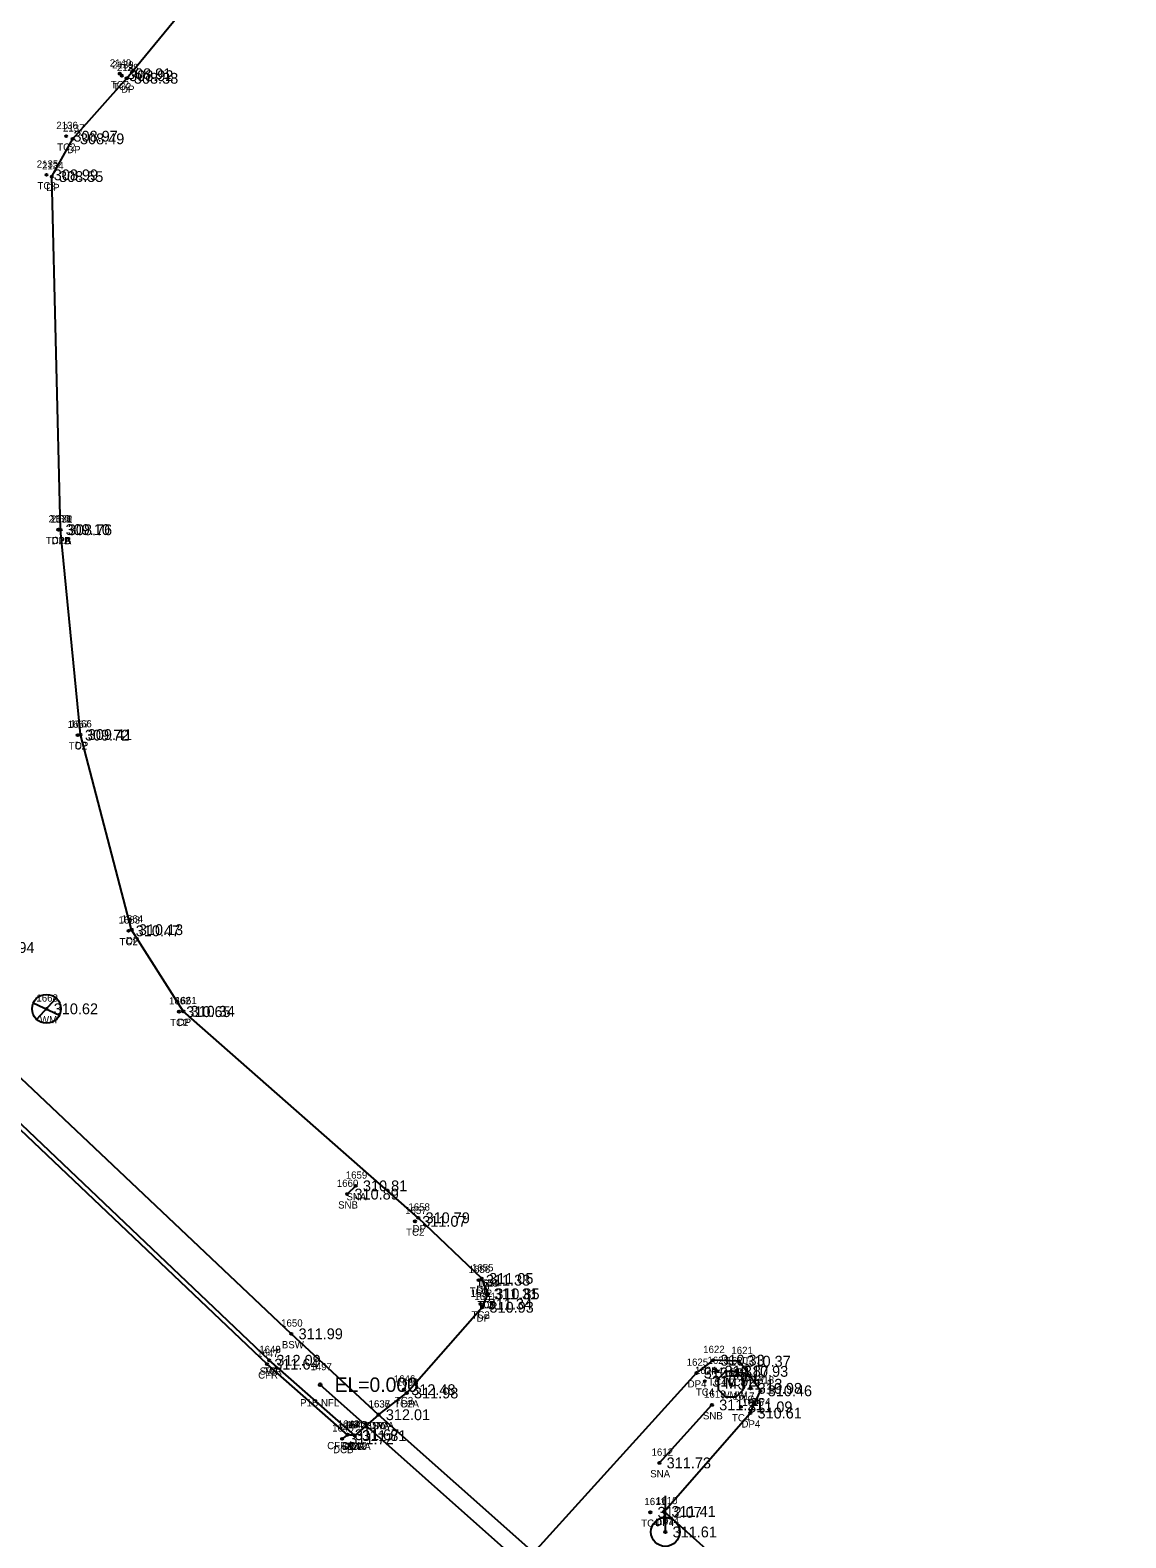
# Model space of a CAD drawing. Extents: x 1970076 to 1971136, y 803126 to 804215.
# Drawn here: x 1970777.2 to 1970928.9, y 803378.3 to 803587.1 of the extents above; entities that cross this region are included whole.
import ezdxf

# ---------------------------------------------------------------- set-up
doc = ezdxf.new("R2010")
doc.units = 0
for name, color, linetype in [('RD_EX_BldgApp', 7, 'Continuous'), ('RD_EX_BldgApp_txCode', 7, 'Continuous'), ('RD_EX_Conc', 7, 'Continuous'), ('RD_EX_Conc_txCode', 7, 'Continuous'), ('RD_EX_DR_Pipe', 7, 'Continuous'), ('RD_EX_DR_Pipe_txCode', 7, 'Continuous'), ('RD_EX_Driveway', 7, 'Continuous'), ('RD_EX_Driveway_txCode', 7, 'Continuous'), ('RD_EX_Misc_txCode', 7, 'Continuous'), ('RD_EX_SU_H2O', 7, 'Continuous'), ('RD_EX_TX_BldgApp_ELEV', 7, 'Continuous'), ('RD_EX_TX_Conc_ELEV', 7, 'Continuous'), ('RD_EX_TX_Driveway_ELEV', 7, 'Continuous'), ('RD_EX_TX_Misc_ELEV', 7, 'Continuous'), ('RD_EX_TX_UT_ELEV', 7, 'Continuous'), ('RD_EX_UT', 7, 'Continuous'), ('RD_EX_UT_txCode', 7, 'Continuous'), ('RD_SMD_Locator', 7, 'Continuous'), ('RD_TX_Pipe_ElevEX', 7, 'Continuous')]:
    doc.layers.add(name, color=color, linetype=linetype)

msp = doc.modelspace()

# ---------------------------------------------------------------- linework, layer by layer
at = {"layer": 'RD_EX_BldgApp'}
for p, q in [((1970822.26, 803427.05), (1970821.09, 803425.91)), ((1970864.31, 803388.69), (1970871.58, 803396.72))]:
    msp.add_line(p, q, dxfattribs=at)
at = {"layer": 'RD_EX_Conc'}
for points in [[(1970822.14, 803392.47), (1970810.28, 803402.9), (1970754.12, 803456.32), (1970718.38, 803492.24), (1970721.52, 803495.16)], [(1970825.43, 803395.36), (1970813.35, 803406.56), (1970757.19, 803459.64), (1970721.52, 803495.16)], [(1970821.14, 803392.59), (1970809.99, 803402.36), (1970753.68, 803455.87), (1970717.79, 803491.63)], [(1970847.44, 803368.09), (1970847.23, 803370.61), (1970846.91, 803376.25), (1970825.43, 803395.36), (1970822.14, 803392.47), (1970821.14, 803392.59), (1970820.38, 803392.03)]]:
    msp.add_lwpolyline(points, dxfattribs=at)
at = {"layer": 'RD_EX_DR_Pipe'}
msp.add_line((1971022.85, 803216.85), (1970817.34, 803399.52), dxfattribs=at)
at = {"layer": 'RD_EX_Driveway'}
for points in [[(1970781.41, 803517.89), (1970780.19, 803566.79), (1970783.09, 803572.02), (1970790.56, 803580.4), (1970803.75, 803596.41), (1970815.3, 803608.83), (1970835.93, 803622.28), (1970852.1, 803631.42), (1970860.94, 803643.71), (1970861.75, 803649.17), (1970862.81, 803650.51), (1970861.9, 803654.38), (1970859.56, 803656.74), (1970855.07, 803659.55), (1970853.81, 803659.78), (1970849.95, 803660.12)], [(1970825.43, 803395.36), (1970829.33, 803398.37), (1970839.78, 803410.24), (1970840.58, 803412.09), (1970839.73, 803414.23), (1970830.93, 803422.63), (1970798.4, 803451.22), (1970791.24, 803462.52), (1970784.17, 803489.53), (1970781.41, 803517.89)], [(1970978.49, 803349.37), (1970974.36, 803344.54), (1970973.43, 803342.01), (1970974.82, 803339.34), (1970978.6, 803335.88), (1970962.13, 803321.3), (1970960.21, 803322.85), (1970957.7, 803323.38), (1970955.12, 803322.32), (1970943.79, 803311.55), (1970935.6, 803318.56), (1970864.97, 803381.97), (1970876.89, 803395.59), (1970878.3, 803398.67), (1970875.35, 803402.77), (1970871.74, 803402.91), (1970869.45, 803401.14), (1970846.9, 803376.22)]]:
    msp.add_lwpolyline(points, dxfattribs=at)
at = {"layer": 'RD_EX_SU_H2O'}
msp.add_lwpolyline([(1970875.95, 803398.85), (1970875.95, 803400.31), (1970874.92, 803401.33), (1970873.47, 803401.33), (1970872.44, 803400.31), (1970872.44, 803398.85), (1970873.47, 803397.83), (1970874.92, 803397.83)], close=True, dxfattribs=at)
at = {"layer": 'RD_EX_UT'}
for p, q in [((1970778.11, 803450.11), (1970780.77, 803453)), ((1970777.63, 803452.4), (1970781.26, 803450.69)), ((1970865.13, 803379.13), (1970865.13, 803384.13))]:
    msp.add_line(p, q, dxfattribs=at)
for centre in [(1970779.46, 803451.56), (1970865.13, 803379.13)]:
    msp.add_circle(centre, 2, dxfattribs=at)
at = {"layer": 'RD_SMD_Locator'}
for centre, radius in [((1970789.6, 803581.03), 0.15), ((1970789.89, 803580.76), 0.15), ((1970790.56, 803580.4), 0.15), ((1970782.19, 803572.38), 0.15), ((1970783.09, 803572.02), 0.15), ((1970779.46, 803567.03), 0.15), ((1970780.19, 803566.79), 0.15), ((1970781.1, 803517.91), 0.15), ((1970781.1, 803517.91), 0.15), ((1970781.41, 803517.89), 0.15), ((1970781.41, 803517.89), 0.15), ((1970783.78, 803489.46), 0.15), ((1970784.17, 803489.53), 0.15), ((1970790.81, 803462.36), 0.15), ((1970791.24, 803462.52), 0.15), ((1970779.46, 803451.56), 0.15), ((1970797.81, 803451.17), 0.15), ((1970798.4, 803451.22), 0.15), ((1970821.09, 803425.91), 0.15), ((1970822.26, 803427.05), 0.15), ((1970830.48, 803422.14), 0.15), ((1970830.93, 803422.63), 0.15), ((1970839.29, 803413.99), 0.15), ((1970839.73, 803414.23), 0.15), ((1970839.54, 803410.68), 0.15), ((1970840.37, 803412.09), 0.15), ((1970840.58, 803412.09), 0.15), ((1970839.78, 803410.24), 0.15), ((1970813.35, 803406.56), 0.15), ((1970809.99, 803402.36), 0.15), ((1970810.28, 803402.9), 0.15), ((1970810.28, 803402.9), 0.15), ((1970871.74, 803402.91), 0.15), ((1970875.35, 803402.77), 0.15), ((1970869.45, 803401.14), 0.15), ((1970872.33, 803401.4), 0.15), ((1970875, 803401.36), 0.15), ((1970817.34, 803399.52), 0.2), ((1970828.94, 803398.83), 0.15), ((1970829.33, 803398.37), 0.15), ((1970829.33, 803398.37), 0.15), ((1970870.6, 803400), 0.15), ((1970874.19, 803399.58), 0.15), ((1970876.91, 803399.01), 0.15), ((1970878.3, 803398.67), 0.15), ((1970871.58, 803396.72), 0.15), ((1970875.59, 803396.45), 0.15), ((1970825.43, 803395.36), 0.15), ((1970825.43, 803395.36), 0.15), ((1970825.43, 803395.36), 0.15), ((1970876.89, 803395.59), 0.15), ((1970820.38, 803392.03), 0.15), ((1970821.14, 803392.59), 0.15), ((1970821.14, 803392.59), 0.15), ((1970822.14, 803392.47), 0.15), ((1970822.14, 803392.47), 0.15), ((1970822.14, 803392.47), 0.15), ((1970864.31, 803388.69), 0.15), ((1970863.04, 803381.85), 0.15), ((1970864.97, 803381.97), 0.15), ((1970865.13, 803379.13), 0.15)]:
    msp.add_circle(centre, radius, dxfattribs=at)

# ---------------------------------------------------------------- texts
at = {"layer": 'RD_EX_BldgApp_txCode'}
for s, p in [('1660', (1970819.65, 803426.91)), ('1659', (1970820.89, 803428.05)), ('SNA', (1970820.99, 803425.05)), ('SNB', (1970819.83, 803423.91)), ('1613', (1970870.49, 803397.72)), ('SNB', (1970870.33, 803394.72)), ('1612', (1970863.22, 803389.69)), ('SNA', (1970863.04, 803386.69))]:
    msp.add_text(s, height=1, dxfattribs=at).set_placement(p)
at = {"layer": 'RD_EX_Conc_txCode'}
for s, p in [('2140', (1970788.22, 803582.03)), ('2139', (1970788.54, 803581.76)), ('TC2', (1970788.36, 803579.03)), ('TC2', (1970788.65, 803578.76)), ('2136', (1970780.82, 803573.38)), ('TC2', (1970780.94, 803570.38)), ('2135', (1970778.11, 803568.03)), ('TC2', (1970778.21, 803565.03)), ('2133', (1970779.75, 803518.91)), ('1671', (1970780.01, 803518.91)), ('TC2A', (1970779.36, 803515.91)), ('TC2B', (1970779.38, 803515.91)), ('1667', (1970782.39, 803490.46)), ('TC2', (1970782.54, 803487.46)), ('1663', (1970789.42, 803463.36)), ('TC2', (1970789.57, 803460.36)), ('1662', (1970796.42, 803452.17)), ('TC2', (1970796.57, 803449.17)), ('1657', (1970829.11, 803423.14)), ('TC2', (1970829.24, 803420.14)), ('1656', (1970837.9, 803414.99)), ('TC2', (1970838.05, 803411.99)), ('1653', (1970839, 803413.09)), ('1652', (1970838.17, 803411.68)), ('TC2', (1970839.13, 803410.09)), ('TC2', (1970838.3, 803408.68)), ('1650', (1970811.94, 803407.56)), ('1648', (1970808.91, 803403.9)), ('1649', (1970808.91, 803403.9)), ('BSW', (1970812.04, 803404.56)), ('1647', (1970808.62, 803403.36)), ('1623', (1970870.96, 803402.4)), ('1620', (1970873.59, 803402.36)), ('CFR', (1970808.76, 803400.36)), ('SWR', (1970808.97, 803400.9)), ('TC', (1970809.49, 803400.9)), ('1646', (1970827.54, 803399.83)), ('1639', (1970827.96, 803399.37)), ('1624', (1970869.23, 803401)), ('TC4', (1970871.08, 803399.4)), ('TC4', (1970873.76, 803399.36)), ('1619', (1970875.82, 803400.01)), ('TC4', (1970869.35, 803398)), ('1617', (1970874.5, 803397.45)), ('1635', (1970824.06, 803396.36)), ('1637', (1970824.06, 803396.36)), ('TC2A', (1970827.6, 803396.37)), ('TC2', (1970827.69, 803396.83)), ('TC4', (1970875.66, 803397.01)), ('1645', (1970819.01, 803393.03)), ('1643', (1970819.77, 803393.59)), ('1644', (1970819.77, 803393.59)), ('1640', (1970820.73, 803393.47)), ('1642', (1970820.77, 803393.47)), ('1641', (1970821.05, 803393.47)), ('BSWA', (1970823.63, 803393.36)), ('DC', (1970824.65, 803393.36)), ('TC4', (1970874.35, 803394.45)), ('CFRA 12', (1970818.32, 803390.59)), ('DCB', (1970819.13, 803390.03)), ('SWRA', (1970820.33, 803390.47)), ('DC', (1970820.36, 803390.59)), ('TCA', (1970820.85, 803390.47)), ('DC', (1970821.36, 803390.47)), ('1611', (1970862.23, 803382.85)), ('TC4', (1970861.79, 803379.85))]:
    msp.add_text(s, height=1, dxfattribs=at).set_placement(p)
at = {"layer": 'RD_EX_DR_Pipe_txCode'}
for s, p in [('1497', (1970816, 803401.52)), ('P1B NFL', (1970814.56, 803396.52))]:
    msp.add_text(s, height=1, dxfattribs=at).set_placement(p)
at = {"layer": 'RD_EX_Driveway_txCode'}
for s, p in [('2138', (1970789.22, 803581.4)), ('DP', (1970789.78, 803578.4)), ('2137', (1970781.74, 803573.02)), ('DP', (1970782.31, 803570.02)), ('2134', (1970778.84, 803567.79)), ('DP', (1970779.41, 803564.79)), ('1670', (1970780, 803518.89)), ('2132', (1970780.06, 803518.89)), ('DPA', (1970780.14, 803515.89)), ('DPB', (1970780.15, 803515.89)), ('1666', (1970782.75, 803490.53)), ('DP', (1970783.39, 803487.53)), ('1664', (1970789.85, 803463.52)), ('DP', (1970790.46, 803460.52)), ('1661', (1970797.28, 803452.22)), ('DP', (1970797.62, 803449.22)), ('1658', (1970829.56, 803423.63)), ('DP', (1970830.15, 803420.63)), ('1655', (1970838.36, 803415.23)), ('DP', (1970838.95, 803412.23)), ('1654', (1970839.21, 803413.09)), ('1651', (1970838.69, 803411.24)), ('DP', (1970839.8, 803410.09)), ('DP', (1970839, 803408.24)), ('1622', (1970870.37, 803403.91)), ('1621', (1970874.27, 803403.77)), ('1625', (1970868.08, 803402.14)), ('1638', (1970827.96, 803399.37)), ('DP4', (1970870.51, 803400.91)), ('DP4', (1970874.12, 803400.77)), ('1618', (1970877.21, 803399.67)), ('DP4', (1970868.22, 803399.14)), ('1636', (1970824.04, 803396.36)), ('DP', (1970828.55, 803396.37)), ('1616', (1970875.78, 803396.59)), ('DP4', (1970877.07, 803396.67)), ('DPA', (1970824.16, 803393.36)), ('DP4', (1970875.67, 803393.59)), ('1610', (1970863.84, 803382.97)), ('DP4', (1970863.74, 803379.97))]:
    msp.add_text(s, height=1, dxfattribs=at).set_placement(p)
at = {"layer": 'RD_EX_Misc_txCode'}
for s, p in [('1615', (1970873.11, 803400.58)), ('WMW', (1970872.75, 803397.58))]:
    msp.add_text(s, height=1, dxfattribs=at).set_placement(p)
at = {"layer": 'RD_EX_SU_H2O'}
msp.add_text('M', height=1.5, dxfattribs=at).set_placement((1970873.36, 803398.97))
at = {"layer": 'RD_EX_TX_BldgApp_ELEV'}
for s, p in [('310.81', (1970823.26, 803426.3)), ('310.89', (1970822.09, 803425.16)), ('311.21', (1970872.58, 803395.97)), ('311.73', (1970865.31, 803387.94))]:
    msp.add_text(s, height=1.5, dxfattribs=at).set_placement(p)
at = {"layer": 'RD_EX_TX_Conc_ELEV'}
for s, p in [('308.91', (1970790.6, 803580.28)), ('308.92', (1970790.89, 803580.01)), ('308.97', (1970783.19, 803571.63)), ('308.99', (1970780.46, 803566.28)), ('309.10', (1970782.1, 803517.16)), ('309.10', (1970782.1, 803517.16)), ('309.72', (1970784.78, 803488.71)), ('310.47', (1970791.81, 803461.61)), ('310.65', (1970798.81, 803450.42)), ('311.07', (1970831.48, 803421.39)), ('311.33', (1970840.29, 803413.24)), ('311.31', (1970841.37, 803411.34)), ('311.34', (1970840.54, 803409.93)), ('311.99', (1970814.35, 803405.81)), ('311.64', (1970810.99, 803401.61)), ('312.09', (1970811.28, 803402.15)), ('312.09', (1970811.28, 803402.15)), ('310.92', (1970871.6, 803399.25)), ('310.87', (1970873.33, 803400.65)), ('310.93', (1970876, 803400.61)), ('312.48', (1970829.94, 803398.08)), ('311.98', (1970830.33, 803397.62)), ('310.98', (1970877.91, 803398.26)), ('312.01', (1970826.43, 803394.61)), ('312.01', (1970826.43, 803394.61)), ('311.09', (1970876.59, 803395.7)), ('311.72', (1970821.38, 803391.28)), ('311.67', (1970822.14, 803391.84)), ('311.67', (1970822.14, 803391.84)), ('311.81', (1970823.14, 803391.72)), ('311.81', (1970823.14, 803391.72)), ('311.81', (1970823.14, 803391.72)), ('312.07', (1970864.04, 803381.1))]:
    msp.add_text(s, height=1.5, dxfattribs=at).set_placement(p)
at = {"layer": 'RD_EX_TX_Driveway_ELEV'}
for s, p in [('308.38', (1970791.56, 803579.65)), ('308.49', (1970784.09, 803571.27)), ('308.55', (1970781.19, 803566.04)), ('308.76', (1970782.41, 803517.14)), ('308.76', (1970782.41, 803517.14)), ('309.41', (1970785.17, 803488.78)), ('310.13', (1970792.24, 803461.77)), ('310.34', (1970799.4, 803450.47)), ('310.79', (1970831.93, 803421.88)), ('311.05', (1970840.73, 803413.48)), ('310.85', (1970841.58, 803411.34)), ('310.93', (1970840.78, 803409.49)), ('310.33', (1970872.74, 803402.16)), ('310.37', (1970876.35, 803402.02)), ('310.48', (1970870.45, 803400.39)), ('311.98', (1970830.33, 803397.62)), ('310.46', (1970879.3, 803397.92)), ('312.01', (1970826.43, 803394.61)), ('310.61', (1970877.89, 803394.84)), ('311.41', (1970865.97, 803381.22))]:
    msp.add_text(s, height=1.5, dxfattribs=at).set_placement(p)
at = {"layer": 'RD_EX_TX_Misc_ELEV'}
msp.add_text('311.13', height=1.5, dxfattribs=at).set_placement((1970875.19, 803398.83))
at = {"layer": 'RD_EX_TX_UT_ELEV'}
for s, p in [('310.94', (1970771.66, 803459.3)), ('310.62', (1970780.46, 803450.81)), ('311.61', (1970866.13, 803378.38))]:
    msp.add_text(s, height=1.5, dxfattribs=at).set_placement(p)
at = {"layer": 'RD_EX_UT_txCode'}
for s, p in [('1668', (1970778.06, 803452.56)), ('WM', (1970778.55, 803449.56)), ('1614', (1970864.04, 803380.13))]:
    msp.add_text(s, height=1, dxfattribs=at).set_placement(p)
at = {"layer": 'RD_TX_Pipe_ElevEX'}
msp.add_text('EL=0.000', height=2, dxfattribs=at).set_placement((1970819.34, 803398.52))

doc.saveas('drawing.dxf')
